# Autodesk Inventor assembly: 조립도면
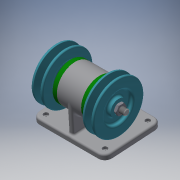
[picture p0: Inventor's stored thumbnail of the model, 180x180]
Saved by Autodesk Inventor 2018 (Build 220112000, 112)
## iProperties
Created: 2019-09
Part Number: 조립도면
Material: 일반
Document SubType Name: Assembly
Designer: USER
Author: USER
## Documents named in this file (10)
- C:\Users\USER\Desktop\490904V1024\조립도면.iam
- C:\Users\USER\Desktop\490904V1024\답안도면.ipt
- C:\Users\USER\Desktop\490904V1024\베어링 6004.ipt
- C:\Users\USER\Desktop\490904V1024\볼트 M4.ipt
- C:\Users\USER\Desktop\490904V1024\오일 실 17 30 5.ipt
- C:\Users\USER\Desktop\490904V1024\축.ipt
- C:\Users\USER\Desktop\490904V1024\커버.ipt
- C:\Users\USER\Desktop\490904V1024\키 5 x 5 x 12.ipt
- C:\Users\USER\Desktop\490904V1024\V-벨트풀리.ipt
- C:\Users\USER\Desktop\490904V1024\너트 M10x1.ipt
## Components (2 placed, 1 different names)
1. V-벨트풀리:1
2. V-벨트풀리:2
